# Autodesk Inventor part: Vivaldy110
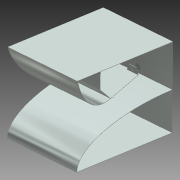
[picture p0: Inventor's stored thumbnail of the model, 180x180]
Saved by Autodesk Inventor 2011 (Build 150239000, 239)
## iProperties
Created: 2014-05
Part Number: Vivaldy110
Document SubType Name: Modeling
Designer: Evgeny
Density: 1 g/cm^3
Author: Evgeny
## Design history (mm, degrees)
sketch "Эскиз1"
  geometry: L1 (-55, 0.25)-(55, 0.25); L2 (55, 0.25)-(55, -0.25); L3 (55, -0.25)-(-55, -0.25); L4 (-55, -0.25)-(-55, 0.25); 1 further point
  constraints: 8 end point, 2 parallel, 1 horizontal, 1 perpendicular
  dimensions: "d0" = 110 distance between parallel lines of L2 L4; "d2" = 0.5 distance between parallel lines of L3 L1; "d3" = 0.25 distance from line of L3 point (0, 0)
sketch "Эскиз2"
  geometry: L1 (-55, 133)-(-55, -7); L2 (-55, -7)-(55, -7); L3 (55, -7)-(55, 133); L4 (0, 60.679)-(0, 0); A1 r 75.048 centre (75.048, 60.679) between (55, 133) and (0, 60.679); 2 further points; 1 other entity
  constraints: 8 end point, 2 point on circle, 2 vertical, 1 centre point, 1 coincident, 1 parallel, 1 tangent, 4 other
  dimensions: "d6" = 110 distance between parallel lines of L3 L1; "d7" = 55 distance from line of L1 L4.end
feature "Сдвиг1" sketch "Эскиз1", "Эскиз2" dims "d8" = 0
sketch "Эскиз4"
  geometry: L1 (-8, -2)-(-58, -2); L2 (-58, -2)-(-58, 140); L3 (-58, 140)-(-8, -2); L4 (8, -2)-(58, 140); L5 (58, 140)-(58, -2); L6 (58, -2)-(8, -2); 1 further point
  constraints: 12 end point, 2 perpendicular, 1 horizontal, 1 parallel
  dimensions: "d9" = 50 distance of L5.end L4.start; "d10" = 50 distance of L1.start L1.end; "d11" = 142 distance of L1.end L2.end; "d12" = 142 distance of L4.end L5.end; "d13" = 8 horizontal distance of L4.start point (0, 0); "d14" = 8 horizontal distance of L1.start point (0, 0)
extrude "Выдавливание1" cut sketch "Эскиз4" distance "d15" = 1; taper "d17" = 0 deg; dims "d16" = 53, "d18" = 0
sketch "Эскиз6"
  geometry: L1 (0, 0)-(0, 0.5) reference; L2 (110, 0)-(0, 0) reference; L3 (0, 0.5)-(110, 0.5) reference; L4 (0, 0.5)-(110, 0.5); L5 (110, 0.5)-(110, 0); L6 (110, 0)-(0, 0); L7 (0, 0)-(0, 0.5); 1 further point
  constraints: 8 end point, 2 parallel, 1 horizontal, 1 perpendicular, 1 point on line
  dimensions: "d24" = 110 distance between parallel lines of L5 L7; "d25" = 0.5 distance between parallel lines of L2 L3 (derived)
extrude "Выдавливание3" join sketch "Эскиз6" distance "d26" = 2; taper "d27" = 0 deg
sketch "Эскиз7"
  geometry: L1 (8.742, 0)-(8.742, 0.212); L2 (8.742, 0.212)-(6, 8); L3 (6, 8)-(-6, 8); L4 (-6, 8)-(-8.701, 0.212); L5 (-8.701, 0.212)-(-8.701, 0); L6 (-8.701, 0)-(8.742, 0); C1 r 1.5 at (0.02, 4); 1 further point
  constraints: 12 end point, 2 parallel, 1 centre point, 1 vertical
  dimensions: "d28" = 3 diameter of C1
extrude "Выдавливание4" join sketch "Эскиз7" distance "d29" = 0.5; taper "d30" = 0 deg
sketch "Эскиз8"
  geometry: C1 r 4.5 at (55, -50.75); 1 further point
  constraints: 1 centre point
  dimensions: "d31" = 9 diameter of C1; "d32" = 4 distance of C1.centre point (55, -54.75)
extrude "Выдавливание5" cut sketch "Эскиз8" distance "d33" = 1; taper "d34" = 0 deg
node "РабПлоскость1"
sketch "Эскиз9"
  geometry: L1 (-30, 0)-(30, 0); L2 (30, 0)-(30, 0.5); L3 (30, 0.5)-(-30, 0.5); L4 (-30, 0.5)-(-30, 0); 1 further point
  constraints: 8 end point, 2 parallel, 1 horizontal, 1 perpendicular
  dimensions: "d35" = 0.75 distance from line of L3 point (0, -0.25); "d36" = 0.5 distance between parallel lines of L1 L3
sketch "Эскиз10"
  geometry: L1 (0.5, 56)-(0.5, 61); L2 (0.5, 61)-(14.914, 75.414); L3 (16.328, 76)-(38.672, 76); L4 (40.086, 75.414)-(54.5, 61); L5 (54.5, 61)-(54.5, 56); L6 (0.25, 0)-(0.25, 60.679) reference; L7 (54.75, 132.671)-(54.75, -6.75) reference; A1 r 2 centre (38.672, 74) between (40.086, 75.414) and (38.672, 76); A2 r 2 centre (16.328, 74) between (16.328, 76) and (14.914, 75.414); 3 further points
  constraints: 10 end point, 4 point on circle, 4 point on line, 4 tangent, 2 centre point, 1 equal radius, 1 parallel, 1 perpendicular, 1 vertical
  dimensions: "d37" = 15 distance from line of L3 L1.end; "d38" = 5 distance of L1.start L1.end; "d39" = 61 vertical distance of L1.end point (0, 0); "d40" = 0.25 distance between parallel lines of L6 L1; "d41" = 15 distance from line of point (15.5, 76) L1; "d42" = 5 distance of L4.end L5.end; "d43" = 0.25 distance between parallel lines of L7 L5; "d44" = 20 distance from line of L5.end L3; "d45" = 15 distance from line of point (39.5, 76) L5; "d46" = 2 radius of A1
feature "Сдвиг2" sketch "Эскиз9", "Эскиз10" dims "d47" = 0
node "Твердое тело1"
